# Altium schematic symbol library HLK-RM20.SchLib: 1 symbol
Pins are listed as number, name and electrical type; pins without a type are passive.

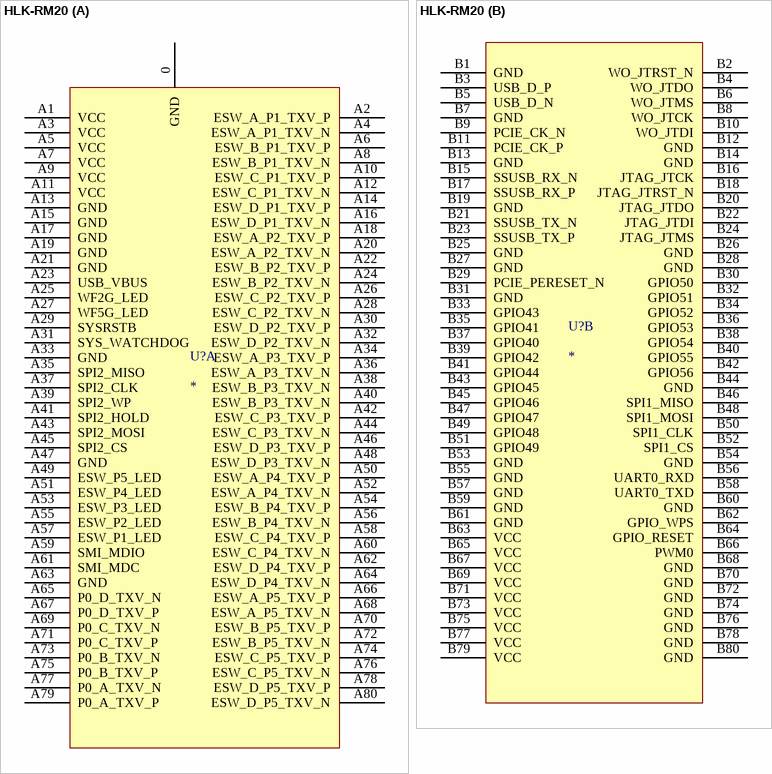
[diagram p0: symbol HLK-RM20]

## HLK-RM20
designator U?
footprint HLK-RM20
part A pins: 0 GND, A1 VCC, A2 ESW_A_P1_TXV_P, A3 VCC, A4 ESW_A_P1_TXV_N, A5 VCC, A6 ESW_B_P1_TXV_P, A7 VCC, A8 ESW_B_P1_TXV_N, A9 VCC, A10 ESW_C_P1_TXV_P, A11 VCC, A12 ESW_C_P1_TXV_N, A13 GND, A14 ESW_D_P1_TXV_P, A15 GND, A16 ESW_D_P1_TXV_N, A17 GND, A18 ESW_A_P2_TXV_P, A19 GND, A20 ESW_A_P2_TXV_N, A21 GND, A22 ESW_B_P2_TXV_P, A23 USB_VBUS, A24 ESW_B_P2_TXV_N, A25 WF2G_LED, A26 ESW_C_P2_TXV_P, A27 WF5G_LED, A28 ESW_C_P2_TXV_N, A29 SYSRSTB, A30 ESW_D_P2_TXV_P, A31 SYS_WATCHDOG, A32 ESW_D_P2_TXV_N, A33 GND, A34 ESW_A_P3_TXV_P, A35 SPI2_MISO, A36 ESW_A_P3_TXV_N, A37 SPI2_CLK, A38 ESW_B_P3_TXV_N, A39 SPI2_WP, A40 ESW_B_P3_TXV_N, A41 SPI2_HOLD, A42 ESW_C_P3_TXV_P, A43 SPI2_MOSI, A44 ESW_C_P3_TXV_N, A45 SPI2_CS, A46 ESW_D_P3_TXV_P, A47 GND, A48 ESW_D_P3_TXV_N, A49 ESW_P5_LED, A50 ESW_A_P4_TXV_P, A51 ESW_P4_LED, A52 ESW_A_P4_TXV_N, A53 ESW_P3_LED, A54 ESW_B_P4_TXV_P, A55 ESW_P2_LED, A56 ESW_B_P4_TXV_N, A57 ESW_P1_LED, A58 ESW_C_P4_TXV_P, A59 SMI_MDIO, A60 ESW_C_P4_TXV_N, A61 SMI_MDC, A62 ESW_D_P4_TXV_P, A63 GND, A64 ESW_D_P4_TXV_N, A65 P0_D_TXV_N, A66 ESW_A_P5_TXV_P, A67 P0_D_TXV_P, A68 ESW_A_P5_TXV_N, A69 P0_C_TXV_N, A70 ESW_B_P5_TXV_P, A71 P0_C_TXV_P, A72 ESW_B_P5_TXV_N, A73 P0_B_TXV_N, A74 ESW_C_P5_TXV_P, A75 P0_B_TXV_P, A76 ESW_C_P5_TXV_N, A77 P0_A_TXV_N, A78 ESW_D_P5_TXV_P, A79 P0_A_TXV_P, A80 ESW_D_P5_TXV_N
part B pins: B1 GND, B2 WO_JTRST_N, B3 USB_D_P, B4 WO_JTDO, B5 USB_D_N, B6 WO_JTMS, B7 GND, B8 WO_JTCK, B9 PCIE_CK_N, B10 WO_JTDI, B11 PCIE_CK_P, B12 GND, B13 GND, B14 GND, B15 SSUSB_RX_N, B16 JTAG_JTCK, B17 SSUSB_RX_P, B18 JTAG_JTRST_N, B19 GND, B20 JTAG_JTDO, B21 SSUSB_TX_N, B22 JTAG_JTDI, B23 SSUSB_TX_P, B24 JTAG_JTMS, B25 GND, B26 GND, B27 GND, B28 GND, B29 PCIE_PERESET_N, B30 GPIO50, B31 GND, B32 GPIO51, B33 GPIO43, B34 GPIO52, B35 GPIO41, B36 GPIO53, B37 GPIO40, B38 GPIO54, B39 GPIO42, B40 GPIO55, B41 GPIO44, B42 GPIO56, B43 GPIO45, B44 GND, B45 GPIO46, B46 SPI1_MISO, B47 GPIO47, B48 SPI1_MOSI, B49 GPIO48, B50 SPI1_CLK, B51 GPIO49, B52 SPI1_CS, B53 GND, B54 GND, B55 GND, B56 UART0_RXD, B57 GND, B58 UART0_TXD, B59 GND, B60 GND, B61 GND, B62 GPIO_WPS, B63 VCC, B64 GPIO_RESET, B65 VCC, B66 PWM0, B67 VCC, B68 GND, B69 VCC, B70 GND, B71 VCC, B72 GND, B73 VCC, B74 GND, B75 VCC, B76 GND, B77 VCC, B78 GND, B79 VCC, B80 GND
